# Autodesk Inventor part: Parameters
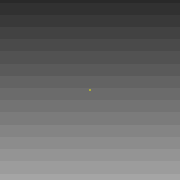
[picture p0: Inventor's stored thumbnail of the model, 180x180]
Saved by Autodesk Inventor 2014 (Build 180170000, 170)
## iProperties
Created: 2013-02
Part Number: Parameters
Document SubType Name: Modeling
Designer: david.appleford
Density: 1 g/cm^3
Material: Generic
Appearance: Default
w: 1220.000 mm
t: 68.000 mm
k1: 16.000 mm
k2: 32.000 mm
kh1: 38.000 mm
kh2: 29.000 mm
ks1: 14.000 mm
Author: david.appleford
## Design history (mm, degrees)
sketch "Sketch1"
  geometry: 1 further point
  dimensions: "w" = 1220 dimension on point (0, 0) [user parameter]
other parameters: "w" = 1220 [user parameter], "t" = 68 [user parameter], "k1" = 16 [user parameter], "k2" = 32 [user parameter], "kh1" = 38 [user parameter], "kh2" = 29 [user parameter], "ks1" = 14 [user parameter]
